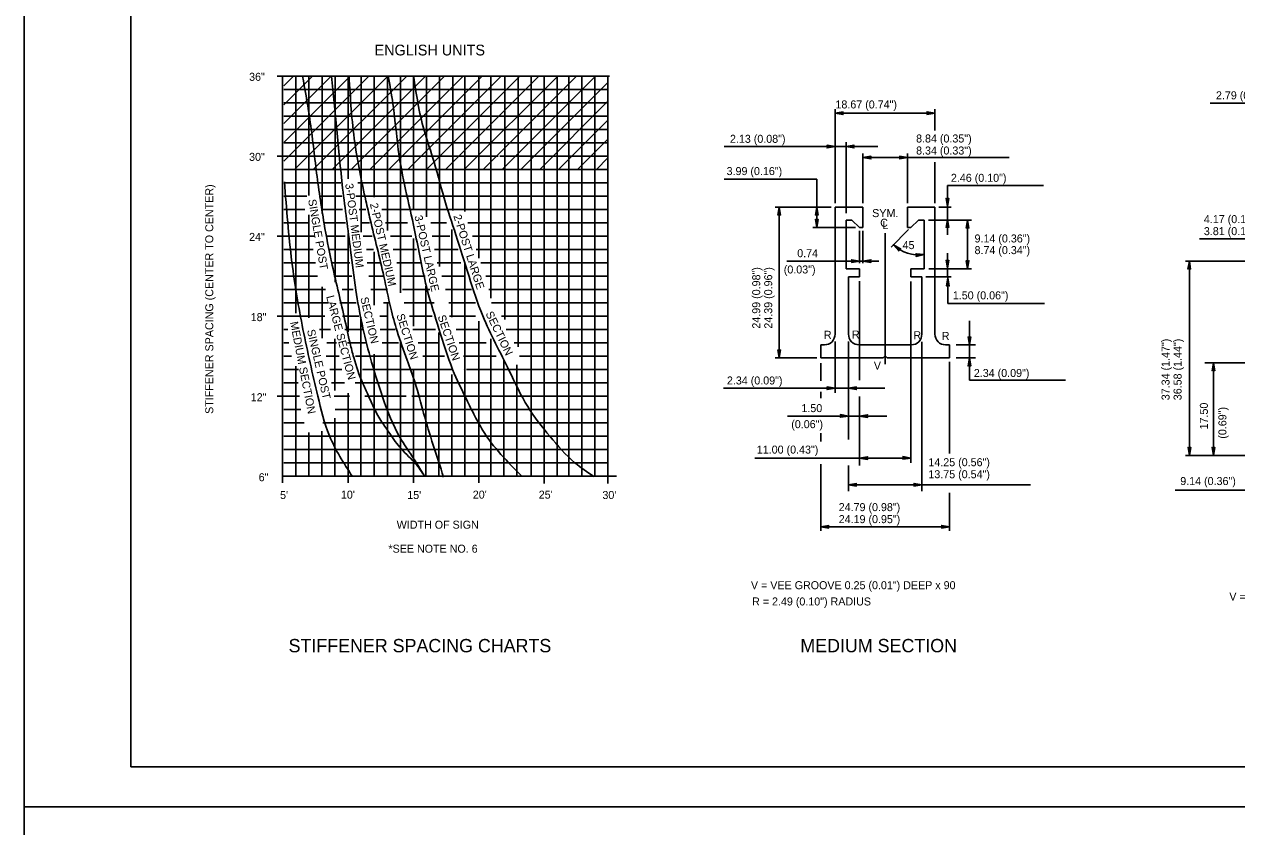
# Model space of a CAD drawing. Extents: x 650495 to 652241, y 298458 to 299646.
# Drawn here: x 650495.3 to 650949.7, y 299044.1 to 299344.9 of the extents above; entities that cross this region are included whole.
import ezdxf

# ---------------------------------------------------------------- set-up
doc = ezdxf.new("R2010")
doc.units = 0
for name, color, linetype in [('1', 7, 'Continuous'), ('2', 7, 'Continuous'), ('3', 7, 'Continuous'), ('PLT-BNDY', 7, 'Continuous')]:
    doc.layers.add(name, color=color, linetype=linetype)

# ---------------------------------------------------------------- blocks, each defined once
blk = doc.blocks.new('RARROW')
at = {"layer": '3'}
blk.add_lwpolyline([(-2.2695, 0.285), (-2.184875, 0.12075), (0, 0), (-2.2695, 0.285), (-2.38575, 0.384625), (0, 0), (-2.183125, -0.108), (-2.262875, -0.2705), (0, 0), (-2.38575, -0.379125), (-2.262875, -0.2705)], dxfattribs=at)

msp = doc.modelspace()

# ---------------------------------------------------------------- linework, layer by layer
at = {"layer": '1'}
for p, q in [((650535.31, 299630.63), (650535.31, 299066.63)), ((651321.31, 299066.63), (650535.31, 299066.63)), ((650535.31, 299066.63), (651121.31, 299066.63))]:
    msp.add_line(p, q, dxfattribs=at)
at = {"layer": '2'}
for p, q in [((650590.03, 299325.48), (650714.65, 299325.48)), ((650592.53, 299321.8), (650596.21, 299325.48)), ((650592.53, 299314.72), (650603.28, 299325.48)), ((650592.53, 299307.65), (650610.36, 299325.48)), ((650592.53, 299300.58), (650617.43, 299325.48)), ((650592.53, 299293.51), (650624.5, 299325.48)), ((650595.28, 299325.48), (650595.28, 299325.48)), ((650596.57, 299290.48), (650631.57, 299325.48)), ((650603.64, 299290.48), (650638.64, 299325.48)), ((650607.53, 299325.48), (650607.53, 299325.48)), ((650610.71, 299290.48), (650645.71, 299325.48)), ((650617.78, 299290.48), (650652.78, 299325.48)), ((650624.85, 299290.48), (650659.85, 299325.48)), ((650625.9, 299325.48), (650625.9, 299325.48)), ((650631.28, 299325.48), (650631.28, 299325.48)), ((650631.92, 299290.48), (650666.92, 299325.48)), ((650639, 299290.48), (650674, 299325.48)), ((650646.07, 299290.48), (650681.07, 299325.48)), ((650653.14, 299290.48), (650688.14, 299325.48)), ((650660.21, 299290.48), (650695.21, 299325.48)), ((650661.15, 299325.48), (650661.15, 299325.48)), ((650667.28, 299290.48), (650702.28, 299325.48)), ((650674.35, 299290.48), (650709.35, 299325.48)), ((650592.53, 299320.48), (650714.03, 299320.48)), ((650607.53, 299320.48), (650607.53, 299320.48)), ((650681.42, 299290.48), (650714.03, 299323.09)), ((650592.53, 299315.48), (650714.03, 299315.48)), ((650632.53, 299317.86), (650632.53, 299317.86)), ((650688.49, 299290.48), (650714.03, 299316.02)), ((650939.78, 299315.27), (650981.53, 299315.27)), ((650799.19, 299277.85), (650799.19, 299313.05)), ((650799.19, 299311.55), (650836.57, 299311.55)), ((650836.57, 299305.04), (650836.57, 299313.05)), ((650592.53, 299310.48), (650714.03, 299310.48)), ((650633.65, 299310.48), (650633.65, 299310.48)), ((650695.56, 299290.48), (650714.03, 299308.95)), ((650592.53, 299305.48), (650714.03, 299305.48)), ((650627.53, 299305.48), (650627.53, 299305.48)), ((650665.15, 299305.48), (650665.15, 299305.48)), ((650702.63, 299290.48), (650714.03, 299301.87)), ((650592.53, 299300.48), (650714.03, 299300.48)), ((650799.19, 299299.03), (650757.59, 299299.03)), ((650815.23, 299299.03), (650799.19, 299299.03)), ((650803.27, 299300.72), (650803.27, 299274.07)), ((650590.03, 299295.48), (650672.9, 299295.48)), ((650597.53, 299295.48), (650597.53, 299295.48)), ((650636.78, 299295.48), (650636.78, 299295.48)), ((650673.53, 299295.48), (650714.03, 299295.48)), ((650709.71, 299290.48), (650714.03, 299294.8)), ((650809.57, 299277.85), (650809.57, 299296.41)), ((650864.46, 299294.91), (650809.57, 299294.91)), ((650826.32, 299277.85), (650826.32, 299296.41)), ((650836.57, 299277.85), (650836.57, 299293.15)), ((650592.53, 299290.48), (650714.03, 299290.48)), ((650609.9, 299290.48), (650609.9, 299290.48)), ((650592.53, 299285.48), (650613.94, 299285.48)), ((650620.28, 299285.48), (650714.03, 299285.48)), ((650792.32, 299286.85), (650757.61, 299286.85)), ((650792.32, 299286.85), (650792.32, 299268.73)), ((650841.26, 299284.47), (650841.26, 299276.59)), ((650841.26, 299284.47), (650877.26, 299284.47)), ((650592.53, 299280.48), (650601.15, 299280.48)), ((650605.9, 299280.48), (650614.33, 299280.48)), ((650619.59, 299280.48), (650714.03, 299280.48)), ((650592.53, 299275.48), (650600.46, 299275.48)), ((650606.9, 299275.48), (650614.53, 299275.48)), ((650612.53, 299275.48), (650612.53, 299275.48)), ((650620.77, 299275.48), (650623.35, 299275.48)), ((650629.3, 299275.48), (650714.03, 299275.48)), ((650797.69, 299276.35), (650776.74, 299276.35)), ((650778.24, 299276.35), (650778.24, 299219.85)), ((650799.19, 299276.35), (650809.57, 299276.35)), ((650799.19, 299276.35), (650799.19, 299228.73)), ((650809.57, 299276.35), (650809.57, 299268.73)), ((650809.57, 299276.35), (650809.57, 299276.35)), ((650836.57, 299276.35), (650826.32, 299276.35)), ((650826.32, 299276.35), (650826.32, 299268.73)), ((650826.32, 299276.35), (650826.32, 299276.35)), ((650836.57, 299228.73), (650836.57, 299276.35)), ((650838.07, 299276.35), (650842.63, 299276.35)), ((650841.26, 299276.59), (650841.26, 299265.99)), ((650592.53, 299270.48), (650601.85, 299270.48)), ((650607.78, 299270.48), (650615.72, 299270.48)), ((650621.67, 299270.48), (650624.74, 299270.48)), ((650630.68, 299270.48), (650638.9, 299270.48)), ((650647.62, 299270.48), (650653.57, 299270.48)), ((650661.5, 299270.48), (650714.03, 299270.48)), ((650805.44, 299271.48), (650803.27, 299271.48)), ((650803.27, 299271.48), (650803.27, 299253.23)), ((650805.44, 299271.48), (650808.32, 299268.73)), ((650830.44, 299271.48), (650827.57, 299268.73)), ((650830.44, 299271.48), (650832.49, 299271.48)), ((650832.49, 299271.48), (650832.49, 299253.23)), ((650834.15, 299271.48), (650850.3, 299271.48)), ((650848.8, 299253.23), (650848.8, 299271.48)), ((650590.03, 299265.48), (650604.15, 299265.48)), ((650608.78, 299265.48), (650615.62, 299265.48)), ((650622.36, 299265.48), (650625.73, 299265.48)), ((650632.57, 299265.48), (650640.53, 299265.48)), ((650648.22, 299265.48), (650654.76, 299265.48)), ((650663.28, 299265.48), (650714.03, 299265.48)), ((650806.82, 299268.73), (650790.82, 299268.73)), ((650809.57, 299268.73), (650808.32, 299268.73)), ((650808.32, 299255.35), (650808.32, 299267.43)), ((650809.57, 299255.35), (650809.57, 299267.43)), ((650817.94, 299217.44), (650817.94, 299266.58)), ((650826.74, 299267.94), (650820.15, 299261.36)), ((650826.32, 299268.73), (650827.57, 299268.73)), ((650935.67, 299264.51), (650971.55, 299264.51)), ((650592.53, 299260.48), (650603.63, 299260.48)), ((650609.65, 299260.48), (650616.65, 299260.48)), ((650623.55, 299260.48), (650626.22, 299260.48)), ((650633.56, 299260.48), (650642.28, 299260.48)), ((650647.53, 299260.48), (650647.53, 299260.48)), ((650649.01, 299260.48), (650657.93, 299260.48)), ((650664.67, 299260.48), (650714.03, 299260.48)), ((650781.14, 299256.1), (650808.32, 299256.1)), ((650808.32, 299256.1), (650815.56, 299256.1)), ((650841.26, 299259.04), (650841.26, 299250.46)), ((650980.03, 299256.15), (650930.42, 299256.15)), ((650931.92, 299256.15), (650931.92, 299183.27)), ((650592.53, 299255.48), (650604.43, 299255.48)), ((650610.65, 299255.48), (650617.31, 299255.48)), ((650623.85, 299255.48), (650628.8, 299255.48)), ((650634.94, 299255.48), (650643.9, 299255.48)), ((650650, 299255.48), (650658.92, 299255.48)), ((650666.45, 299255.48), (650714.03, 299255.48)), ((650803.27, 299253.23), (650808.32, 299253.23)), ((650808.32, 299253.23), (650808.32, 299250.23)), ((650832.49, 299253.23), (650827.57, 299253.23)), ((650827.57, 299253.23), (650827.57, 299250.23)), ((650834.26, 299253.23), (650850.3, 299253.23)), ((650592.53, 299250.48), (650605.22, 299250.48)), ((650611.65, 299250.48), (650618.1, 299250.48)), ((650624.44, 299250.48), (650629.99, 299250.48)), ((650636.13, 299250.48), (650645.53, 299250.48)), ((650651.79, 299250.48), (650660.31, 299250.48)), ((650668.23, 299250.48), (650714.03, 299250.48)), ((650804.19, 299228.73), (650804.19, 299250.23)), ((650804.19, 299250.23), (650808.32, 299250.23)), ((650808.32, 299248.62), (650808.32, 299211.44)), ((650827.57, 299250.23), (650831.69, 299250.23)), ((650827.57, 299180.46), (650827.57, 299248.44)), ((650831.69, 299250.23), (650831.69, 299228.73)), ((650833.19, 299250.23), (650842.63, 299250.23)), ((650841.44, 299249.8), (650841.44, 299240.21)), ((650592.53, 299245.48), (650608.15, 299245.48)), ((650614.43, 299245.48), (650618.6, 299245.48)), ((650625.23, 299245.48), (650631.38, 299245.48)), ((650637.12, 299245.48), (650647.28, 299245.48)), ((650653.17, 299245.48), (650662.88, 299245.48)), ((650669.42, 299245.48), (650714.03, 299245.48)), ((650592.53, 299240.48), (650609.15, 299240.48)), ((650607.53, 299240.48), (650607.53, 299240.48)), ((650613.53, 299240.48), (650619.69, 299240.48)), ((650629.9, 299240.48), (650632.37, 299240.48)), ((650637.72, 299240.48), (650648.9, 299240.48)), ((650654.36, 299240.48), (650664.47, 299240.48)), ((650670.41, 299240.48), (650714.03, 299240.48)), ((650841.44, 299240.21), (650877.62, 299240.21)), ((650590.03, 299235.48), (650607.9, 299235.48)), ((650592.53, 299235.48), (650592.53, 299235.48)), ((650614.53, 299235.48), (650620.68, 299235.48)), ((650628.6, 299235.48), (650631.18, 299235.48)), ((650639.7, 299235.48), (650648.22, 299235.48)), ((650648.78, 299235.48), (650648.78, 299235.48)), ((650654.65, 299235.48), (650664.47, 299235.48)), ((650674.18, 299235.48), (650714.03, 299235.48)), ((650849.5, 299219.85), (650849.5, 299233.78)), ((650592.53, 299230.48), (650594.12, 299230.48)), ((650605.91, 299230.48), (650610.07, 299230.48)), ((650615.4, 299230.48), (650622.36, 299230.48)), ((650634.25, 299230.48), (650628.7, 299230.48)), ((650640.89, 299230.48), (650649.41, 299230.48)), ((650657.14, 299230.48), (650665.85, 299230.48)), ((650675.96, 299230.48), (650714.03, 299230.48)), ((650592.53, 299225.48), (650594.52, 299225.48)), ((650608.69, 299225.48), (650612.28, 299225.48)), ((650616.4, 299225.48), (650623.75, 299225.48)), ((650635.54, 299225.48), (650629.39, 299225.48)), ((650642.87, 299225.48), (650650.6, 299225.48)), ((650658.32, 299225.48), (650668.43, 299225.48)), ((650678.93, 299225.48), (650714.03, 299225.48)), ((650795.19, 299224.73), (650793.82, 299224.73)), ((650793.82, 299224.73), (650793.82, 299219.85)), ((650799.19, 299225.98), (650799.19, 299206.72)), ((650804.19, 299225.98), (650804.19, 299189.21)), ((650827.69, 299224.73), (650808.19, 299224.73)), ((650831.69, 299225.88), (650831.69, 299169.88)), ((650842.07, 299224.73), (650840.57, 299224.73)), ((650842.07, 299219.85), (650842.07, 299224.73)), ((650851.84, 299224.73), (650844.54, 299224.73)), ((650592.53, 299220.48), (650595.51, 299220.48)), ((650608.49, 299220.48), (650613.28, 299220.48)), ((650619.39, 299220.48), (650635.93, 299220.48)), ((650644.65, 299220.48), (650652.78, 299220.48)), ((650659.91, 299220.48), (650672.2, 299220.48)), ((650680.91, 299220.48), (650714.03, 299220.48)), ((650708.9, 299220.48), (650708.9, 299220.48)), ((650792.32, 299219.85), (650776.74, 299219.85)), ((650793.82, 299219.85), (650817.19, 299219.85)), ((650818.69, 299219.85), (650842.07, 299219.85)), ((650844.54, 299219.85), (650851.84, 299219.85)), ((650849.5, 299211.53), (650849.5, 299219.85)), ((650592.53, 299215.48), (650598.03, 299215.48)), ((650609.88, 299215.48), (650614.28, 299215.48)), ((650612.53, 299215.48), (650612.53, 299215.48)), ((650622.06, 299215.48), (650655.45, 299215.48)), ((650659.9, 299215.48), (650659.9, 299215.48)), ((650661, 299215.48), (650714.03, 299215.48)), ((650793.82, 299217.85), (650793.82, 299211.21)), ((650842.07, 299218.35), (650842.07, 299184.05)), ((650963.28, 299218.03), (650937.68, 299218.03)), ((650940.92, 299218.03), (650940.92, 299183.27)), ((650849.5, 299211.53), (650885.5, 299211.53)), ((650592.53, 299210.48), (650597.99, 299210.48)), ((650610.47, 299210.48), (650615.28, 299210.48)), ((650619.28, 299210.48), (650714.03, 299210.48)), ((650799.19, 299208.48), (650757.31, 299208.48)), ((650793.82, 299207.17), (650793.82, 299204.7)), ((650817.87, 299208.48), (650799.19, 299208.48)), ((650590.03, 299205.48), (650598.48, 299205.48)), ((650597.53, 299205.48), (650597.53, 299205.48)), ((650611.46, 299205.48), (650617.21, 299205.48)), ((650622.95, 299205.48), (650638.4, 299205.48)), ((650640.53, 299205.48), (650714.03, 299205.48)), ((650808.32, 299205.38), (650808.32, 299179.49)), ((650592.53, 299200.48), (650598.98, 299200.48)), ((650611.86, 299200.48), (650714.03, 299200.48)), ((650781.32, 299198.06), (650804.19, 299198.06)), ((650818.6, 299198.06), (650804.19, 299198.06)), ((650592.53, 299195.48), (650600.27, 299195.48)), ((650607.15, 299195.48), (650714.03, 299195.48)), ((650642.53, 299195.48), (650642.53, 299195.48)), ((650686.78, 299195.48), (650686.78, 299195.48)), ((650592.53, 299190.48), (650714.03, 299190.48)), ((650692.53, 299190.48), (650692.53, 299190.48)), ((650793.82, 299191.57), (650793.82, 299188.45)), ((650592.53, 299185.48), (650714.03, 299185.48)), ((650627.53, 299185.48), (650627.53, 299185.48)), ((650650.15, 299185.48), (650650.15, 299185.48)), ((650687.53, 299185.48), (650687.53, 299185.48)), ((650699.9, 299185.48), (650699.9, 299185.48)), ((650592.53, 299180.48), (650714.03, 299180.48)), ((650607.53, 299180.48), (650607.53, 299180.48)), ((650827.57, 299182.32), (650769.12, 299182.32)), ((650793.82, 299180.01), (650793.82, 299155.03)), ((650804.19, 299179.56), (650804.19, 299169.88)), ((650963.28, 299183.27), (650930.42, 299183.27)), ((650592.15, 299175.48), (650717.28, 299175.48)), ((650712.53, 299175.48), (650712.53, 299175.48)), ((650804.19, 299172.3), (650872.37, 299172.3)), ((650926.56, 299170.3), (650983.03, 299170.3)), ((650842.07, 299169.23), (650842.07, 299155.03)), ((650793.82, 299156.53), (650842.07, 299156.53))]:
    msp.add_line(p, q, dxfattribs=at)
for points in [[(650592.15, 299325.48), (650592.15, 299172.98)], [(650597.03, 299325.48), (650597.03, 299236.61)], [(650601.9, 299325.48), (650601.9, 299280.74)], [(650606.9, 299325.48), (650606.9, 299273.98)], [(650611.78, 299325.48), (650611.78, 299248.23)], [(650616.65, 299325.48), (650616.65, 299286.98)], [(650621.53, 299325.48), (650621.53, 299266.96)], [(650626.4, 299325.48), (650626.4, 299280.04)], [(650631.4, 299325.48), (650631.4, 299267.56)], [(650636.28, 299325.48), (650636.28, 299244.17)], [(650641.15, 299325.48), (650641.15, 299275.36)], [(650646.03, 299325.48), (650646.03, 299272.71)], [(650650.9, 299325.48), (650650.9, 299254.08)], [(650655.9, 299325.48), (650655.9, 299275.09)], [(650660.4, 299325.48), (650660.4, 299274.69)], [(650665.65, 299325.48), (650665.65, 299257.25)], [(650670.15, 299325.48), (650670.15, 299242.19)], [(650675.4, 299325.48), (650675.4, 299234.26)], [(650680.4, 299325.48), (650680.4, 299223.95)], [(650685.28, 299325.48), (650685.28, 299175.48)], [(650690.15, 299325.48), (650690.15, 299172.81)], [(650695.03, 299325.48), (650695.03, 299175.48)], [(650699.4, 299325.48), (650699.4, 299175.48)], [(650704.28, 299325.48), (650704.28, 299175.48)], [(650709.15, 299325.48), (650709.15, 299175.48)], [(650714.03, 299325.48), (650714.03, 299172.77)], [(650601.9, 299273.4), (650601.9, 299234.86)], [(650616.65, 299266.47), (650616.65, 299229.6)], [(650655.53, 299267.95), (650655.53, 299235.05)], [(650641.15, 299264.61), (650641.15, 299231.68)], [(650626.4, 299259.63), (650626.4, 299239.61)], [(650660.4, 299255.47), (650660.4, 299175.48)], [(650606.9, 299246.45), (650606.9, 299227.22)], [(650645.78, 299246.75), (650645.78, 299175.48)], [(650631.4, 299240.6), (650631.4, 299175.48)], [(650621.4, 299235.05), (650621.4, 299175.48)], [(650665.65, 299233.66), (650665.65, 299172.98)], [(650650.65, 299229.3), (650650.65, 299175.48)], [(650611.65, 299226.98), (650611.65, 299207.6)], [(650636.28, 299225.93), (650636.28, 299175.48)], [(650670.15, 299226.93), (650670.15, 299175.48)], [(650626.4, 299221.18), (650626.4, 299175.48)], [(650817.19, 299219.85), (650817.94, 299220.6), (650818.69, 299219.85)], [(650597.03, 299216.72), (650597.03, 299175.48)], [(650641.15, 299215.63), (650641.15, 299172.98)], [(650675.03, 299219), (650675.03, 299175.48)], [(650679.9, 299217.21), (650679.9, 299175.48)], [(650655.53, 299213.65), (650655.53, 299175.48)], [(650616.65, 299206.61), (650616.65, 299172.98)], [(650611.65, 299197.29), (650611.65, 299175.48)], [(650606.78, 299192.44), (650606.78, 299175.48)], [(650601.9, 299191.84), (650601.9, 299175.48)]]:
    msp.add_lwpolyline(points, dxfattribs=at)
for centre, radius, start, end in [((650830.27, 299271.48), 13.06, 225.0095, 279.8021), ((650795.19, 299228.73), 4, 270, 0), ((650808.19, 299228.73), 4, 180, 270), ((650827.69, 299228.73), 4, 270, 0), ((650840.57, 299228.73), 4, 180, 270)]:
    msp.add_arc(centre, radius, start, end, dxfattribs=at)
for points in [[(650599.57, 299325.48), (650602.15, 299310.57), (650604.72, 299290.35), (650607.7, 299270.13), (650610.47, 299255.86), (650612.85, 299245.36), (650615.23, 299235.05), (650617.41, 299225.34), (650618.79, 299219.99), (650622.16, 299210.28), (650624.14, 299205.92), (650626.52, 299200.76), (650629.3, 299195.81), (650632.27, 299191.45), (650636.63, 299185.7), (650641.98, 299180.15), (650645.35, 299175.48)], [(650610.47, 299325.48), (650612.45, 299305.41), (650614.63, 299283.41), (650617.6, 299260.22), (650619.59, 299245.16), (650624.94, 299220.19), (650629.69, 299204.93), (650636.23, 299189.86), (650640.59, 299183.12), (650645.35, 299175.48)], [(650617.01, 299325.48), (650619.19, 299300.48), (650623.35, 299278.66), (650624.94, 299271.72), (650630.09, 299250.31), (650632.66, 299238.52), (650635.04, 299229.9), (650638.81, 299219), (650641.78, 299210.48), (650644.95, 299199.18), (650652.48, 299175.2)], [(650631.67, 299325.48), (650633.46, 299315.12), (650635.83, 299295.5), (650638.61, 299281.23), (650641.98, 299265.77), (650646.34, 299245.36), (650650.7, 299230.69), (650655.85, 299215.43), (650661, 299204.33), (650664.17, 299197.99), (650667.14, 299192.64), (650681.81, 299175.48)], [(650641.18, 299325.48), (650645.15, 299305.22), (650648.32, 299295.11), (650652.68, 299279.65), (650657.04, 299265.97), (650661.99, 299250.31), (650667.14, 299235.65), (650677.05, 299215.03), (650683.99, 299201.56), (650692.31, 299190.46), (650701.62, 299180.55), (650708.75, 299175.39)], [(650592.84, 299285.79), (650595.61, 299255.66), (650599.77, 299230.49), (650605.32, 299205.52), (650609.68, 299190.66), (650618.2, 299175.48)]]:
    msp.add_spline(points, degree=3, dxfattribs=at)
at = {"layer": 'PLT-BNDY'}
for points in [[(650495.31, 299645.63), (651336.31, 299645.63), (651336.31, 299051.63), (650495.31, 299051.63)], [(650495.31, 299051.63), (651336.31, 299051.63), (651336.31, 298457.63), (650495.31, 298457.63)]]:
    msp.add_lwpolyline(points, close=True, dxfattribs=at)

# ---------------------------------------------------------------- block references
at = {"layer": '2', "xscale": 1.2574347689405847}
for p, yscale, rotation in [((650799.19, 299311.55), 1.3092961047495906, 180), ((650803.27, 299299.03), 1.3092961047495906, 180), ((650809.57, 299294.91), 1.3092961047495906, 180), ((650841.26, 299276.59), 1.3092961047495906, -90.00000000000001), ((650778.24, 299276.35), 1.3092961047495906, 89.99999999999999), ((650792.32, 299276.35), 1.3092961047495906, 89.99999999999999), ((650792.32, 299268.73), 1.3092961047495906, -90.00000000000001), ((650841.26, 299271.71), 1.3092961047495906, 89.99999999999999), ((650848.8, 299271.48), 1.3092961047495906, 89.99999999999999), ((650821.04, 299262.24), 1.3092961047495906, 140.9194989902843), ((650809.57, 299256.1), 1.3092961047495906, 180), ((650832.49, 299258.61), 1.3092961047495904, 4.175089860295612), ((650841.26, 299253.46), 1.3092961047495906, -90.00000000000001), ((650848.8, 299253.23), 1.3092961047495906, -90.00000000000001), ((650931.92, 299256.15), 1.3092961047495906, 89.99999999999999), ((650841.44, 299249.8), 1.3092961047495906, 89.99999999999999), ((650849.5, 299224.73), 1.3092961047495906, -90.00000000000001), ((650778.24, 299219.85), 1.3092961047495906, -90.00000000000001), ((650849.5, 299219.85), 1.3092961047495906, 89.99999999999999), ((650940.92, 299218.03), 1.3092961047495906, 89.99999999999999), ((650804.19, 299208.48), 1.3092961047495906, 180), ((650808.32, 299198.06), 1.3092961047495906, 180), ((650931.92, 299183.27), 1.3092961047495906, -90.00000000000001), ((650940.92, 299183.27), 1.3092961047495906, -90.00000000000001), ((650808.32, 299182.32), 1.3092961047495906, 180), ((650804.19, 299172.3), 1.3092961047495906, 180), ((650793.82, 299156.53), 1.3092961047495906, 180)]:
    msp.add_blockref('RARROW', p, dxfattribs=dict(at, yscale=yscale, rotation=rotation))
at = {"layer": '2', "xscale": 1.2574347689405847, "yscale": 1.3092961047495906}
for p in [(650836.57, 299311.55), (650799.19, 299299.03), (650826.32, 299294.91), (650808.32, 299256.1), (650799.19, 299208.48), (650804.19, 299198.06), (650827.57, 299182.32), (650831.69, 299172.3), (650842.07, 299156.53)]:
    msp.add_blockref('RARROW', p, dxfattribs=at)

# ---------------------------------------------------------------- texts
at = {"layer": '2'}
for s, height, p in [('ENGLISH UNITS', 4.0375, (650626.58, 299333.19)), ('2.79 (0.11")', 3, (650941.89, 299316.74)), ('18.67 (0.74")', 3, (650799.3, 299313.32)), ('2.13 (0.08")', 3, (650759.77, 299300.44)), ('8.84 (0.35")', 3, (650829.52, 299300.56)), ('8.34 (0.33")', 3, (650829.52, 299296.06)), ('3.99 (0.16")', 3, (650758.51, 299288.35)), ('2.46 (0.10")', 3, (650842.57, 299285.82)), ('SYM.', 3, (650813.07, 299272.6)), ('C', 3, (650816.07, 299268.98)), ('L', 3, (650816.94, 299268.1)), ('4.17 (0.17")', 3, (650937.37, 299270.34)), ('9.14 (0.36")', 3, (650851.43, 299263.1)), ('3.81 (0.15")', 3, (650937.37, 299265.84)), ('0.74', 3, (650784.98, 299257.57)), ('45', 3, (650824.45, 299260.61)), ('8.74 (0.34")', 3, (650851.43, 299258.73)), ('(0.03")', 3, (650779.94, 299251.48)), ('1.50 (0.06")', 3, (650843.29, 299241.78)), ('R', 3, (650794.97, 299226.98)), ('R', 3, (650805.47, 299227.1)), ('R', 3, (650828.5, 299226.85)), ('R', 3, (650839.14, 299226.57)), ('V', 3, (650813.69, 299215.43)), ('2.34 (0.09")', 3, (650851.16, 299212.68)), ('2.34 (0.09")', 3, (650758.63, 299209.88)), ('1.50', 3, (650786.55, 299199.52)), ('(0.06")', 3, (650782.74, 299193.5)), ('11.00 (0.43")', 3, (650769.83, 299183.97)), ('14.25 (0.56")', 3, (650834.13, 299179.24)), ('13.75 (0.54")', 3, (650834.13, 299174.74)), ('9.14 (0.36")', 3, (650928.52, 299172.18)), ('24.79 (0.98")', 3, (650800.52, 299162.41)), ('24.19 (0.95")', 3, (650800.52, 299157.91)), ('WIDTH OF SIGN', 3, (650634.88, 299155.83)), ('*SEE NOTE NO. 6', 3, (650631.78, 299146.83)), ('V = VEE GROOVE 0.25 (0.01") DEEP x 90', 3, (650767.63, 299133.15)), ('R = 2.49 (0.10") RADIUS', 3, (650768.06, 299127.06)), ('V = VEE GROOVE 0.38 (0.015") DEEP x 90', 3, (650946.91, 299128.9)), ('STIFFENER SPACING CHARTS', 5, (650594.37, 299109.5)), ('MEDIUM SECTION', 5, (650786.15, 299109.51))]:
    msp.add_text(s, height=height, dxfattribs=at).set_placement(p)
for s, height, rotation, p in [('STIFFENER SPACING (CENTER TO CENTER)', 3, 90, (650566.15, 299198.84)), ('3-POST MEDIUM', 2.9992, 277.2906, (650615.57, 299285.05)), ('SINGLE POST', 3, 279.7906, (650601.68, 299279.06)), ('2-POST MEDIUM', 3, 282.7906, (650624.81, 299277.53)), ('3-POST LARGE', 3, 282.7906, (650641.5, 299272.94)), ('2-POST LARGE', 3, 287.7906, (650656.08, 299273.04)), ('24.99 (0.98")', 3, 90, (650771.11, 299230.8)), ('24.39 (0.96")', 3, 90, (650775.61, 299230.8)), ('LARGE SECTION', 3, 284.7906, (650608.43, 299242.83)), ('SECTION', 2.999, 283.2906, (650621.22, 299242.27)), ('MEDIUM SECTION', 3, 281.0612, (650594.91, 299233.18)), ('SECTION', 3, 287.7906, (650634.73, 299235.86)), ('SECTION', 3, 288.7906, (650650.18, 299235.37)), ('SECTION', 3, 295.7906, (650668.11, 299236.44)), ('SINGLE POST', 3, 283.0612, (650601.24, 299230.16)), ('37.34 (1.47")', 3, 90, (650924.51, 299203.97)), ('36.58 (1.44")', 3, 90, (650929.01, 299203.97)), ('17.50', 3, 90, (650938.86, 299193.03)), (' (0.69") ', 3, 90, (650945.81, 299188.44))]:
    msp.add_text(s, height=height, rotation=rotation, dxfattribs=at).set_placement(p)
at = {"layer": '3'}
for s, p in [('36"', (650579.57, 299323.68)), ('30"', (650579.57, 299293.68)), ('24"', (650579.57, 299263.68)), ('18"', (650580.18, 299233.61)), ('12"', (650580.18, 299203.61)), ('6"', (650583.16, 299173.61)), ("5'", (650591.18, 299166.95)), ("10'", (650613.97, 299167.09)), ("15'", (650638.83, 299166.95)), ("20'", (650663.4, 299167.09)), ("25'", (650688.11, 299167.09)), ("30'", (650711.97, 299166.95))]:
    msp.add_text(s, height=3, dxfattribs=at).set_placement(p)

doc.saveas('drawing.dxf')
